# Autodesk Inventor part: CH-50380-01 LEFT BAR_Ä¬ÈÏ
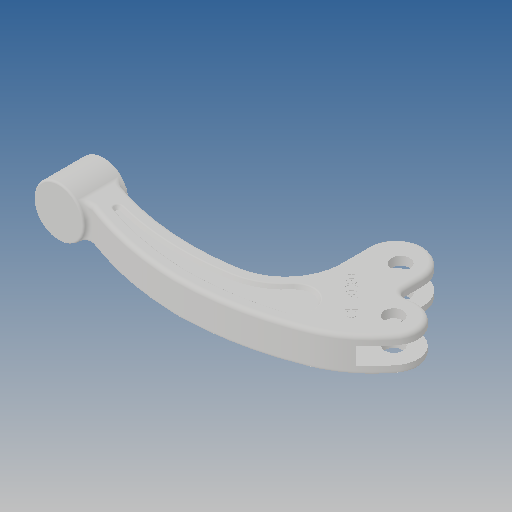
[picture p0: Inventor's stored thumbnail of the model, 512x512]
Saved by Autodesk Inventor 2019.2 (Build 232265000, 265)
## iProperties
Created: 2010-06
Part Number: CH-50380-01 LEFT BAR_Ä¬ÈÏ
Material: Ogólny
Document SubType Name: Modeling
Designer: CADENGINEERING4
Density: 1 g/cm^3
Appearance: Domyślna
Author: CADENGINEERING4
Revision Number: ÈÎºÎ
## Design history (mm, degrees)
feature "NONE"
node "Bryła1"
